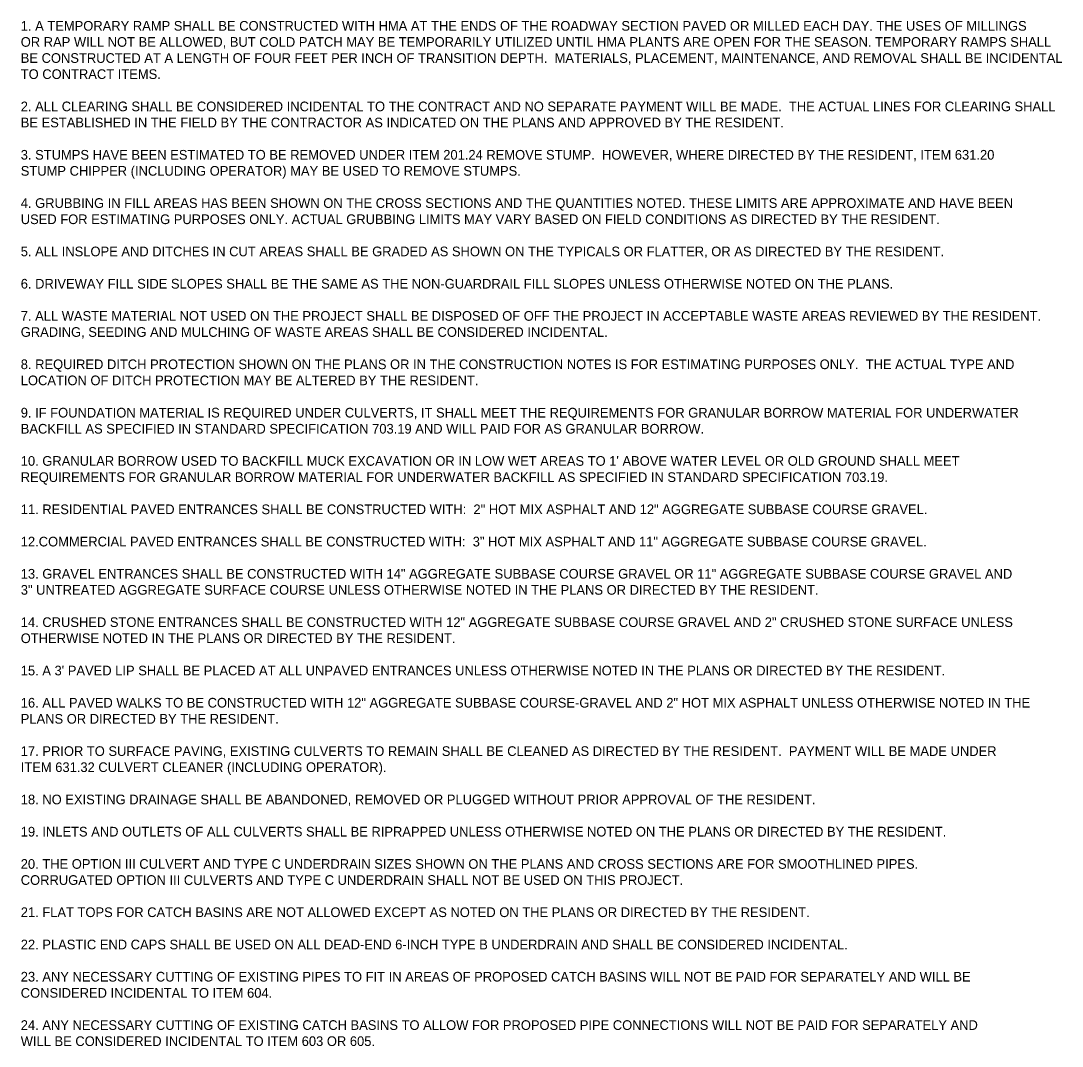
# Model space of a CAD drawing. Extents: x -0.13 to 5.88, y -0.37 to 1.78.
# Drawn here: x 4.829 to 5.839, y 0.643 to 1.637 of the extents above; entities that cross this region are included whole.
import ezdxf

# ---------------------------------------------------------------- set-up
doc = ezdxf.new("R2010")
doc.units = 0
doc.layers.add('ANNOTATION', color=7, linetype='Continuous')

msp = doc.modelspace()

# ---------------------------------------------------------------- texts
at = {"layer": 'ANNOTATION'}
for s, p in [('1. A TEMPORARY RAMP SHALL BE CONSTRUCTED WITH HMA AT THE ENDS OF THE ROADWAY SECTION PAVED OR MILLED EACH DAY. THE USES OF MILLINGS', (4.8293, 1.627)), ('OR RAP WILL NOT BE ALLOWED, BUT COLD PATCH MAY BE TEMPORARILY UTILIZED UNTIL HMA PLANTS ARE OPEN FOR THE SEASON. TEMPORARY RAMPS SHALL', (4.8293, 1.6114)), ('BE CONSTRUCTED AT A LENGTH OF FOUR FEET PER INCH OF TRANSITION DEPTH.  MATERIALS, PLACEMENT, MAINTENANCE, AND REMOVAL SHALL BE INCIDENTAL', (4.8293, 1.5958)), ('TO CONTRACT ITEMS.', (4.8293, 1.5802)), ('2. ALL CLEARING SHALL BE CONSIDERED INCIDENTAL TO THE CONTRACT AND NO SEPARATE PAYMENT WILL BE MADE.  THE ACTUAL LINES FOR CLEARING SHALL', (4.8293, 1.5489)), ('BE ESTABLISHED IN THE FIELD BY THE CONTRACTOR AS INDICATED ON THE PLANS AND APPROVED BY THE RESIDENT.', (4.8293, 1.5333)), ('3. STUMPS HAVE BEEN ESTIMATED TO BE REMOVED UNDER ITEM 201.24 REMOVE STUMP.  HOWEVER, WHERE DIRECTED BY THE RESIDENT, ITEM 631.20', (4.8293, 1.502)), ('STUMP CHIPPER (INCLUDING OPERATOR) MAY BE USED TO REMOVE STUMPS.   ', (4.8293, 1.4864)), ('4. GRUBBING IN FILL AREAS HAS BEEN SHOWN ON THE CROSS SECTIONS AND THE QUANTITIES NOTED. THESE LIMITS ARE APPROXIMATE AND HAVE BEEN', (4.8293, 1.4552)), ('USED FOR ESTIMATING PURPOSES ONLY. ACTUAL GRUBBING LIMITS MAY VARY BASED ON FIELD CONDITIONS AS DIRECTED BY THE RESIDENT. ', (4.8293, 1.4395)), ('5. ALL INSLOPE AND DITCHES IN CUT AREAS SHALL BE GRADED AS SHOWN ON THE TYPICALS OR FLATTER, OR AS DIRECTED BY THE RESIDENT.', (4.8293, 1.4083)), ('6. DRIVEWAY FILL SIDE SLOPES SHALL BE THE SAME AS THE NON-GUARDRAIL FILL SLOPES UNLESS OTHERWISE NOTED ON THE PLANS.', (4.8293, 1.377)), ('7. ALL WASTE MATERIAL NOT USED ON THE PROJECT SHALL BE DISPOSED OF OFF THE PROJECT IN ACCEPTABLE WASTE AREAS REVIEWED BY THE RESIDENT.', (4.8293, 1.3458)), ('GRADING, SEEDING AND MULCHING OF WASTE AREAS SHALL BE CONSIDERED INCIDENTAL.', (4.8293, 1.3302)), ('8. REQUIRED DITCH PROTECTION SHOWN ON THE PLANS OR IN THE CONSTRUCTION NOTES IS FOR ESTIMATING PURPOSES ONLY.  THE ACTUAL TYPE AND', (4.8293, 1.2989)), ('LOCATION OF DITCH PROTECTION MAY BE ALTERED BY THE RESIDENT.', (4.8293, 1.2833)), ('9. IF FOUNDATION MATERIAL IS REQUIRED UNDER CULVERTS, IT SHALL MEET THE REQUIREMENTS FOR GRANULAR BORROW MATERIAL FOR UNDERWATER', (4.8293, 1.252)), ('BACKFILL AS SPECIFIED IN STANDARD SPECIFICATION 703.19 AND WILL PAID FOR AS GRANULAR BORROW.', (4.8293, 1.2364)), ("10. GRANULAR BORROW USED TO BACKFILL MUCK EXCAVATION OR IN LOW WET AREAS TO 1' ABOVE WATER LEVEL OR OLD GROUND SHALL MEET", (4.8293, 1.2052)), ('REQUIREMENTS FOR GRANULAR BORROW MATERIAL FOR UNDERWATER BACKFILL AS SPECIFIED IN STANDARD SPECIFICATION 703.19.', (4.8293, 1.1895)), ('11. RESIDENTIAL PAVED ENTRANCES SHALL BE CONSTRUCTED WITH:  2" HOT MIX ASPHALT AND 12" AGGREGATE SUBBASE COURSE GRAVEL.', (4.8293, 1.1583)), ('12.COMMERCIAL PAVED ENTRANCES SHALL BE CONSTRUCTED WITH:  3" HOT MIX ASPHALT AND 11" AGGREGATE SUBBASE COURSE GRAVEL.', (4.8293, 1.127)), ('13. GRAVEL ENTRANCES SHALL BE CONSTRUCTED WITH 14" AGGREGATE SUBBASE COURSE GRAVEL OR 11" AGGREGATE SUBBASE COURSE GRAVEL AND', (4.8293, 1.0958)), ('3" UNTREATED AGGREGATE SURFACE COURSE UNLESS OTHERWISE NOTED IN THE PLANS OR DIRECTED BY THE RESIDENT.', (4.8293, 1.0802)), ('14. CRUSHED STONE ENTRANCES SHALL BE CONSTRUCTED WITH 12" AGGREGATE SUBBASE COURSE GRAVEL AND 2" CRUSHED STONE SURFACE UNLESS', (4.8293, 1.0489)), ('OTHERWISE NOTED IN THE PLANS OR DIRECTED BY THE RESIDENT.', (4.8293, 1.0333)), ("15. A 3' PAVED LIP SHALL BE PLACED AT ALL UNPAVED ENTRANCES UNLESS OTHERWISE NOTED IN THE PLANS OR DIRECTED BY THE RESIDENT.", (4.8293, 1.002)), ('16. ALL PAVED WALKS TO BE CONSTRUCTED WITH 12" AGGREGATE SUBBASE COURSE-GRAVEL AND 2" HOT MIX ASPHALT UNLESS OTHERWISE NOTED IN THE', (4.8293, 0.9708)), ('PLANS OR DIRECTED BY THE RESIDENT.', (4.8293, 0.9552)), ('17. PRIOR TO SURFACE PAVING, EXISTING CULVERTS TO REMAIN SHALL BE CLEANED AS DIRECTED BY THE RESIDENT.  PAYMENT WILL BE MADE UNDER', (4.8293, 0.9239)), ('ITEM 631.32 CULVERT CLEANER (INCLUDING OPERATOR).', (4.8293, 0.9083)), ('18. NO EXISTING DRAINAGE SHALL BE ABANDONED, REMOVED OR PLUGGED WITHOUT PRIOR APPROVAL OF THE RESIDENT.', (4.8293, 0.877)), ('19. INLETS AND OUTLETS OF ALL CULVERTS SHALL BE RIPRAPPED UNLESS OTHERWISE NOTED ON THE PLANS OR DIRECTED BY THE RESIDENT.', (4.8293, 0.8458)), ('20. THE OPTION III CULVERT AND TYPE C UNDERDRAIN SIZES SHOWN ON THE PLANS AND CROSS SECTIONS ARE FOR SMOOTHLINED PIPES.', (4.8293, 0.8145)), ('CORRUGATED OPTION III CULVERTS AND TYPE C UNDERDRAIN SHALL NOT BE USED ON THIS PROJECT.', (4.8293, 0.7989)), ('21. FLAT TOPS FOR CATCH BASINS ARE NOT ALLOWED EXCEPT AS NOTED ON THE PLANS OR DIRECTED BY THE RESIDENT.', (4.8293, 0.7677)), ('22. PLASTIC END CAPS SHALL BE USED ON ALL DEAD-END 6-INCH TYPE B UNDERDRAIN AND SHALL BE CONSIDERED INCIDENTAL.', (4.8293, 0.7364)), ('23. ANY NECESSARY CUTTING OF EXISTING PIPES TO FIT IN AREAS OF PROPOSED CATCH BASINS WILL NOT BE PAID FOR SEPARATELY AND WILL BE', (4.8293, 0.7052)), ('CONSIDERED INCIDENTAL TO ITEM 604.', (4.8293, 0.6895)), ('24. ANY NECESSARY CUTTING OF EXISTING CATCH BASINS TO ALLOW FOR PROPOSED PIPE CONNECTIONS WILL NOT BE PAID FOR SEPARATELY AND', (4.8293, 0.6583)), ('WILL BE CONSIDERED INCIDENTAL TO ITEM 603 OR 605.', (4.8293, 0.6427))]:
    msp.add_text(s, height=0.009375, dxfattribs=at).set_placement(p)

doc.saveas('drawing.dxf')
